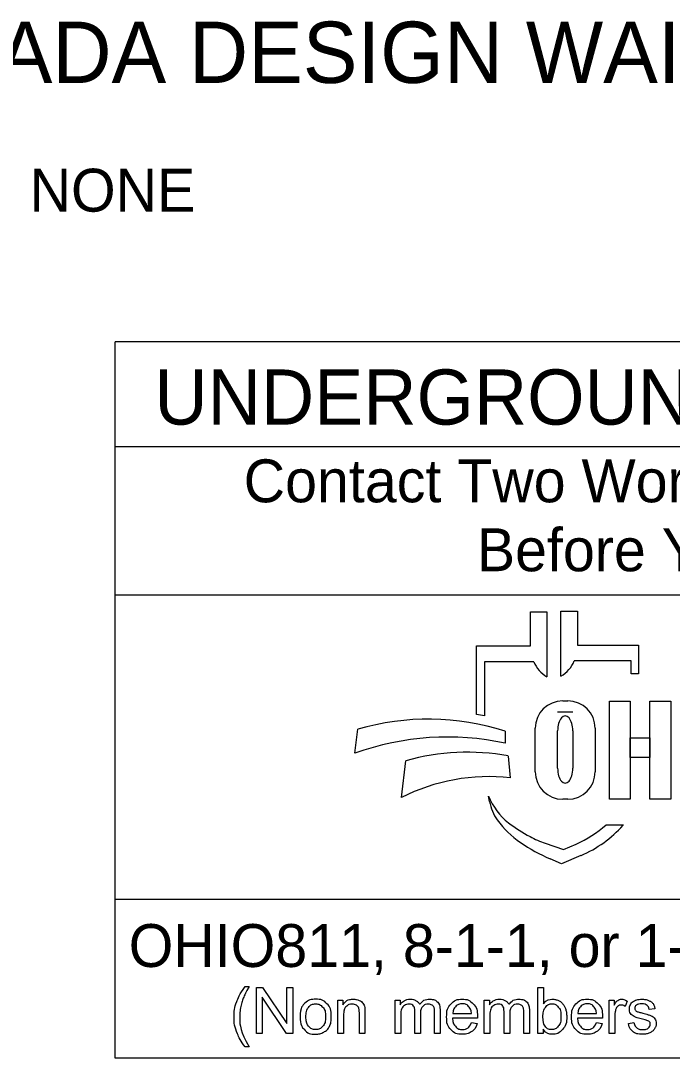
# Model space of a CAD drawing. Extents: x -31.7 to 34, y 0 to 22.
# Drawn here: x 2.07 to 4.196, y 2.143 to 5.529 of the extents above; entities that cross this region are included whole.
import ezdxf

# ---------------------------------------------------------------- set-up
doc = ezdxf.new("R2010")
doc.units = 0
doc.layers.add('SH_Data', color=7, linetype='Continuous')
doc.layers.add('SH_Text', color=7, linetype='Continuous')

msp = doc.modelspace()

# ---------------------------------------------------------------- linework, layer by layer
at = {"layer": 'SH_Data'}
for p, q in [((2.3775, 2.1428), (2.3775, 4.4803)), ((6.6275, 4.4803), (2.3775, 4.4803)), ((2.3775, 4.1387), (6.6275, 4.1387)), ((2.3775, 3.6553), (6.6275, 3.6553)), ((6.6275, 2.6607), (2.3775, 2.6607)), ((6.6275, 2.1428), (2.3775, 2.1428))]:
    msp.add_line(p, q, dxfattribs=at)
at = {"layer": 'SH_Text'}
for p, q in [((3.7335, 3.4883), (3.7335, 3.5998)), ((3.7335, 3.5998), (3.7872, 3.5998)), ((3.7872, 3.5998), (3.7872, 3.3877)), ((3.8329, 3.39), (3.8329, 3.6021)), ((3.8329, 3.6021), (3.8865, 3.6021)), ((3.8865, 3.6021), (3.8865, 3.4906)), ((3.5576, 3.2644), (3.5576, 3.4883)), ((3.5576, 3.4883), (3.7335, 3.4883)), ((3.8865, 3.4906), (4.0857, 3.4906)), ((4.0857, 3.4906), (4.0857, 3.3968)), ((3.5828, 3.4369), (3.5828, 3.26)), ((3.7439, 3.4369), (3.5828, 3.4369)), ((4.0625, 3.4392), (3.8761, 3.4392)), ((4.0625, 3.3968), (4.0625, 3.4392)), ((4.0857, 3.3968), (4.0625, 3.3968)), ((3.8385, 3.3091), (3.8551, 3.3091)), ((3.8718, 3.2721), (3.822, 3.2721)), ((3.7491, 3.0776), (3.7491, 3.2196)), ((3.9445, 3.2196), (3.9445, 3.0776)), ((3.1602, 3.1381), (3.1696, 3.2162)), ((3.6509, 3.2097), (3.6509, 3.1709)), ((3.822, 3.089), (3.822, 3.2114)), ((3.8718, 3.2114), (3.8718, 3.089)), ((3.6608, 3.1291), (3.6671, 3.0582)), ((3.312, 2.9936), (3.3267, 3.1137)), ((3.5997, 2.9807), (3.5967, 2.9986)), ((3.8551, 2.9882), (3.8385, 2.9882)), ((3.98, 2.9048), (4.0375, 2.9048)), ((3.7816, 2.8444), (3.841, 2.8239)), ((3.841, 2.8239), (3.8821, 2.8417)), ((3.835, 2.7769), (3.7976, 2.7934)), ((3.8983, 2.8044), (3.835, 2.7769))]:
    msp.add_line(p, q, dxfattribs=at)
for points in [[(3.991, 3.3081), (4.0589, 3.3081), (4.0589, 2.9881), (3.991, 2.9881)], [(4.1231, 3.3081), (4.1911, 3.3081), (4.1911, 2.9881), (4.1231, 2.9881)], [(4.0589, 3.1882), (4.1231, 3.1882), (4.1231, 3.1242), (4.0589, 3.1242)]]:
    msp.add_lwpolyline(points, close=True, dxfattribs=at)
for points in [[(2.8021, 2.3766), (2.8153, 2.3766)], [(2.8389, 2.2239), (2.8389, 2.3741), (2.8592, 2.3741), (2.9382, 2.2561), (2.9382, 2.3741), (2.9572, 2.3741), (2.9572, 2.2239), (2.9369, 2.2239), (2.8579, 2.3419), (2.8579, 2.2239), (2.8389, 2.2239)], [(3.7743, 2.2239), (3.7573, 2.2239), (3.7573, 2.3741), (3.7757, 2.3741), (3.7757, 2.3206)], [(3.1048, 2.2239), (3.1048, 2.3328), (3.1214, 2.3328), (3.1214, 2.3173)], [(3.2912, 2.2239), (3.2912, 2.3328), (3.3077, 2.3328), (3.3077, 2.3174)], [(3.5826, 2.2239), (3.5826, 2.3328), (3.5991, 2.3328), (3.5991, 2.3174)], [(3.9904, 2.2239), (3.9904, 2.3328), (4.007, 2.3328), (4.007, 2.3163)], [(4.0495, 2.3293), (4.043, 2.3122)], [(4.1394, 2.3046), (4.1213, 2.3022)], [(3.1233, 2.2833), (3.1233, 2.2239), (3.1048, 2.2239)], [(3.1932, 2.2908), (3.1932, 2.2239), (3.1748, 2.2239), (3.1748, 2.2901)], [(3.3097, 2.2803), (3.3097, 2.2239), (3.2912, 2.2239)], [(3.3743, 2.2871), (3.3743, 2.2239), (3.3559, 2.2239), (3.3559, 2.2946)], [(3.4388, 2.2986), (3.4388, 2.2239), (3.4203, 2.2239), (3.4203, 2.2924)], [(3.56, 2.2736), (3.4788, 2.2736)], [(3.4799, 2.2887), (3.5406, 2.2887)], [(3.601, 2.2803), (3.601, 2.2239), (3.5826, 2.2239)], [(3.6657, 2.2871), (3.6657, 2.2239), (3.6473, 2.2239), (3.6473, 2.2946)], [(3.7301, 2.2986), (3.7301, 2.2239), (3.7117, 2.2239), (3.7117, 2.2924)], [(3.968, 2.2736), (3.8868, 2.2736)], [(3.8879, 2.2887), (3.9486, 2.2887)], [(4.0088, 2.2809), (4.0088, 2.2239), (3.9904, 2.2239)], [(3.5404, 2.2591), (3.5595, 2.2567)], [(3.7743, 2.2375), (3.7743, 2.2239)], [(3.9484, 2.2591), (3.9675, 2.2567)], [(4.053, 2.2564), (4.0712, 2.2593)], [(2.8153, 2.1798), (2.8021, 2.1798)]]:
    msp.add_lwpolyline(points, dxfattribs=at)
for centre, radius, start, end in [((3.8353, 3.4736), 0.0985, 201.9296, 240.7469), ((3.7847, 3.476), 0.0985, 299.2531, 338.0704), ((3.8385, 3.2196), 0.0895, 90, 180), ((3.8551, 3.2196), 0.0895, 0, 90), ((3.4295, 2.4554), 0.8191, 79.2074, 81.0007), ((3.3997, 2.4302), 0.8191, 72.1402, 106.3144), ((3.4628, 2.2991), 0.8919, 77.8238, 109.8274), ((3.5267, 2.4094), 0.7322, 79.44, 105.8467), ((3.5987, 2.4262), 0.6357, 83.8248, 116.8021), ((3.8385, 3.0776), 0.0895, 180, 270), ((3.8551, 3.0776), 0.0895, 270, 0), ((3.7841, 3.0707), 0.2008, 201.0457, 232.5314), ((3.741, 3.0048), 0.1433, 189.6817, 216.0884), ((3.8747, 3.1022), 0.3088, 216.0884, 235.7167), ((3.9766, 3.3219), 0.5173, 232.5314, 241.794), ((3.7387, 3.1722), 0.3602, 293.4582, 312.0712), ((3.7387, 3.1722), 0.401, 293.4582, 317.8286), ((4.0412, 3.3465), 0.6044, 235.7167, 246.2325), ((3.8914, 3.1631), 0.3371, 241.794, 250.9821)]:
    msp.add_arc(centre, radius, start, end, dxfattribs=at)
for centre, start_param, end_param in [((3.8469, 3.2114), 4.712389, 7.853982), ((3.8469, 3.089), 1.570796, 4.712389)]:
    msp.add_ellipse(centre, major_axis=(0, 0.0484), ratio=0.514403, start_param=start_param, end_param=end_param, dxfattribs=at)
for points in [[(2.8021, 2.1798), (2.7869, 2.199), (2.7763, 2.2248), (2.7657, 2.2506), (2.7657, 2.2783), (2.7657, 2.3026), (2.7736, 2.325), (2.7829, 2.3509), (2.8021, 2.3766)], [(2.8153, 2.3766), (2.8029, 2.3553), (2.7989, 2.3462), (2.7927, 2.332), (2.7891, 2.3167), (2.7847, 2.2975), (2.7847, 2.2782), (2.7847, 2.2289), (2.8153, 2.1798)], [(2.9814, 2.2783), (2.9814, 2.3085), (2.9981, 2.3231), (3.0122, 2.3352), (3.0323, 2.3352), (3.0547, 2.3352), (3.069, 2.3205), (3.0832, 2.3058), (3.0832, 2.2799), (3.0832, 2.2589), (3.0769, 2.2469), (3.0706, 2.2348), (3.0586, 2.2282), (3.0466, 2.2215), (3.0323, 2.2215), (3.0095, 2.2215), (2.9954, 2.2362), (2.9814, 2.2508), (2.9814, 2.2783)], [(3.0003, 2.2783), (3.0003, 2.2574), (3.0094, 2.247), (3.0185, 2.2366), (3.0323, 2.2366), (3.046, 2.2366), (3.0551, 2.2471), (3.0642, 2.2575), (3.0642, 2.279), (3.0642, 2.2991), (3.0551, 2.3095), (3.0459, 2.3199), (3.0323, 2.3199), (3.0185, 2.3199), (3.0094, 2.3096), (3.0003, 2.2992), (3.0003, 2.2783)], [(3.1214, 2.3173), (3.1334, 2.3352), (3.156, 2.3352), (3.1659, 2.3352), (3.1741, 2.3316), (3.1823, 2.3281), (3.1864, 2.3224), (3.1905, 2.3166), (3.1922, 2.3087), (3.1932, 2.3036), (3.1932, 2.2908)], [(3.1748, 2.2901), (3.1748, 2.3013), (3.1726, 2.3069), (3.1705, 2.3125), (3.165, 2.3158), (3.1595, 2.3191), (3.1521, 2.3191), (3.1404, 2.3191), (3.1318, 2.3117), (3.1233, 2.3042), (3.1233, 2.2833)], [(3.3077, 2.3174), (3.3128, 2.3254), (3.3214, 2.3303), (3.3299, 2.3352), (3.3407, 2.3352), (3.3528, 2.3352), (3.3606, 2.3301), (3.3683, 2.3251), (3.3715, 2.3161), (3.3844, 2.3352), (3.4051, 2.3352), (3.4213, 2.3352), (3.43, 2.3262), (3.4388, 2.3172), (3.4388, 2.2986)], [(3.3559, 2.2946), (3.3559, 2.3069), (3.3514, 2.313), (3.3469, 2.3191), (3.3366, 2.3191), (3.3288, 2.3191), (3.3222, 2.315), (3.3156, 2.311), (3.3126, 2.3031), (3.3097, 2.2952), (3.3097, 2.2803)], [(3.4203, 2.2924), (3.4203, 2.3035), (3.4185, 2.3083), (3.4168, 2.3132), (3.412, 2.3162), (3.4073, 2.3191), (3.401, 2.3191), (3.3895, 2.3191), (3.3819, 2.3115), (3.3743, 2.3039), (3.3743, 2.2871)], [(3.5595, 2.2567), (3.555, 2.24), (3.5428, 2.2307), (3.5306, 2.2215), (3.5117, 2.2215), (3.4878, 2.2215), (3.4738, 2.2362), (3.4598, 2.2509), (3.4598, 2.2774), (3.4598, 2.3049), (3.474, 2.32), (3.4881, 2.3352), (3.5106, 2.3352), (3.5324, 2.3352), (3.5463, 2.3203), (3.5601, 2.3055), (3.5601, 2.2785), (3.5601, 2.2769), (3.56, 2.2736)], [(3.5406, 2.2887), (3.5394, 2.3025), (3.5337, 2.3094), (3.5249, 2.3201), (3.5108, 2.3201), (3.4981, 2.3201), (3.4894, 2.3115), (3.4808, 2.303), (3.4799, 2.2887)], [(3.5991, 2.3174), (3.6042, 2.3254), (3.6127, 2.3303), (3.6212, 2.3352), (3.6321, 2.3352), (3.6442, 2.3352), (3.6519, 2.3301), (3.6597, 2.3251), (3.6628, 2.3161), (3.6758, 2.3352), (3.6965, 2.3352), (3.7127, 2.3352), (3.7214, 2.3262), (3.7301, 2.3172), (3.7301, 2.2986)], [(3.6473, 2.2946), (3.6473, 2.3069), (3.6428, 2.313), (3.6383, 2.3191), (3.628, 2.3191), (3.6202, 2.3191), (3.6136, 2.315), (3.607, 2.311), (3.604, 2.3031), (3.601, 2.2952), (3.601, 2.2803)], [(3.7117, 2.2924), (3.7117, 2.3035), (3.7099, 2.3083), (3.7081, 2.3132), (3.7034, 2.3162), (3.6987, 2.3191), (3.6923, 2.3191), (3.6809, 2.3191), (3.6733, 2.3115), (3.6657, 2.3039), (3.6657, 2.2871)], [(3.7741, 2.2792), (3.7741, 2.2596), (3.7794, 2.2509), (3.7881, 2.2366), (3.8029, 2.2366), (3.815, 2.2366), (3.8238, 2.2471), (3.8326, 2.2576), (3.8326, 2.2784), (3.8326, 2.2998), (3.8241, 2.3099), (3.8157, 2.3201), (3.8038, 2.3201), (3.7917, 2.3201), (3.7829, 2.3096), (3.7741, 2.299), (3.7741, 2.2792)], [(3.7757, 2.3206), (3.7874, 2.3352), (3.8055, 2.3352), (3.8155, 2.3352), (3.8245, 2.3311), (3.8335, 2.3271), (3.8392, 2.3198), (3.845, 2.3124), (3.8483, 2.3021), (3.8516, 2.2918), (3.8516, 2.28), (3.8516, 2.252), (3.8378, 2.2368), (3.8239, 2.2215), (3.8046, 2.2215), (3.7853, 2.2215), (3.7743, 2.2375)], [(3.9675, 2.2567), (3.963, 2.24), (3.9508, 2.2307), (3.9386, 2.2215), (3.9196, 2.2215), (3.8958, 2.2215), (3.8818, 2.2362), (3.8678, 2.2509), (3.8678, 2.2774), (3.8678, 2.3049), (3.882, 2.32), (3.8961, 2.3352), (3.9186, 2.3352), (3.9404, 2.3352), (3.9543, 2.3203), (3.9681, 2.3055), (3.9681, 2.2785), (3.9681, 2.2769), (3.968, 2.2736)], [(3.9486, 2.2887), (3.9474, 2.3025), (3.9417, 2.3094), (3.9328, 2.3201), (3.9188, 2.3201), (3.9061, 2.3201), (3.8974, 2.3115), (3.8888, 2.303), (3.8879, 2.2887)], [(4.007, 2.3163), (4.0133, 2.3278), (4.0187, 2.3315), (4.0241, 2.3352), (4.0305, 2.3352), (4.0398, 2.3352), (4.0495, 2.3293)], [(4.043, 2.3122), (4.0363, 2.3162), (4.0295, 2.3162), (4.0235, 2.3162), (4.0187, 2.3125), (4.0139, 2.3089), (4.0119, 2.3024), (4.0088, 2.2926), (4.0088, 2.2809)], [(4.1213, 2.3022), (4.1201, 2.3106), (4.1142, 2.3153), (4.1083, 2.3201), (4.0975, 2.3201), (4.0848, 2.3201), (4.0794, 2.3159), (4.0739, 2.3116), (4.0739, 2.306), (4.0739, 2.3024), (4.0762, 2.2995), (4.0785, 2.2966), (4.0833, 2.2946), (4.086, 2.2936), (4.0996, 2.2899), (4.1192, 2.2847), (4.1269, 2.2813), (4.1347, 2.278), (4.1391, 2.2717), (4.1435, 2.2653), (4.1435, 2.2559), (4.1435, 2.2467), (4.1381, 2.2386), (4.1327, 2.2304), (4.1226, 2.226), (4.1124, 2.2215), (4.0996, 2.2215), (4.0784, 2.2215), (4.0672, 2.2303), (4.0561, 2.2391), (4.053, 2.2564)], [(4.0712, 2.2593), (4.0727, 2.2483), (4.0798, 2.2425), (4.0868, 2.2366), (4.0995, 2.2366), (4.1122, 2.2366), (4.1184, 2.2418), (4.1245, 2.247), (4.1245, 2.254), (4.1245, 2.2602), (4.1191, 2.2638), (4.1153, 2.2663), (4.1002, 2.2701), (4.0799, 2.2752), (4.072, 2.2789), (4.0642, 2.2827), (4.0601, 2.2893), (4.0561, 2.2959), (4.0561, 2.3038), (4.0561, 2.3111), (4.0594, 2.3173), (4.0628, 2.3235), (4.0685, 2.3276), (4.0728, 2.3308), (4.0803, 2.333), (4.0877, 2.3352), (4.0962, 2.3352), (4.109, 2.3352), (4.1187, 2.3315), (4.1284, 2.3278), (4.133, 2.3215), (4.1377, 2.3152), (4.1394, 2.3046)], [(3.4788, 2.2736), (3.4799, 2.2557), (3.489, 2.2462), (3.4981, 2.2366), (3.5117, 2.2366), (3.5219, 2.2366), (3.5291, 2.242), (3.5362, 2.2473), (3.5404, 2.2591)], [(3.8868, 2.2736), (3.8879, 2.2557), (3.897, 2.2462), (3.9061, 2.2366), (3.9197, 2.2366), (3.9299, 2.2366), (3.937, 2.242), (3.9442, 2.2473), (3.9484, 2.2591)]]:
    msp.add_open_spline(points, degree=3, dxfattribs=at)

# ---------------------------------------------------------------- texts
for s, height, p in [('ADA DESIGN WAIVERS', 0.2, (1.9944, 5.3256)), ('  NONE', 0.14, (1.9944, 4.9056)), ('UNDERGROUND UTILITIES', 0.18, (2.5057, 4.2106)), ('Contact Two Working Days', 0.14, (2.7972, 3.9571)), ('Before You Dig', 0.14, (3.5583, 3.7321)), ('OHIO811, 8-1-1, or 1-800-362-2764', 0.14, (2.422, 2.4406))]:
    msp.add_text(s, height=height, dxfattribs=at).set_placement(p)

doc.saveas('drawing.dxf')
